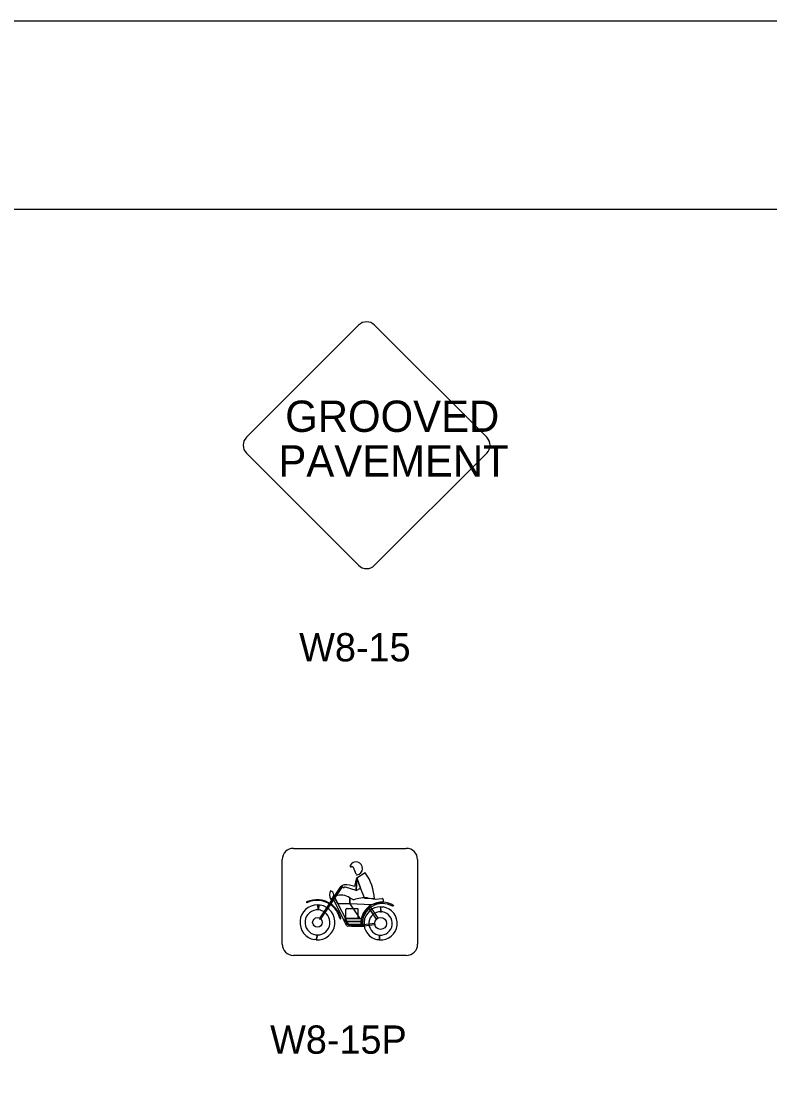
# Model space of a CAD drawing. Extents: x 42133 to 45533, y 41351 to 47951.
# Drawn here: x 44937.5 to 45136.1, y 47671.7 to 47951.4 of the extents above; entities that cross this region are included whole.
import ezdxf

# ---------------------------------------------------------------- set-up
doc = ezdxf.new("R2010")
doc.units = 0
for name, color, linetype in [('#plot_shape', 7, 'Continuous'), ('P_ODOT_PLAN_Border', 7, 'Continuous'), ('P_TRAF_SIGN_SignDetails', 7, 'Continuous')]:
    doc.layers.add(name, color=color, linetype=linetype)

msp = doc.modelspace()

# ---------------------------------------------------------------- linework, layer by layer
at = {"layer": '#plot_shape'}
msp.add_lwpolyline([(43833.34, 46851.35), (45533.34, 46851.35), (45533.34, 47951.35), (43833.34, 47951.35)], close=True, dxfattribs=at)
at = {"layer": 'P_ODOT_PLAN_Border'}
msp.add_lwpolyline([(43908.34, 46901.35), (45508.34, 46901.35), (45508.34, 47901.35), (43908.34, 47901.35)], close=True, dxfattribs=at)
at = {"layer": 'P_TRAF_SIGN_SignDetails'}
for p, q in [((45027.03, 47870.64), (44997.29, 47840.9)), ((45061.02, 47840.9), (45031.28, 47870.64)), ((44997.29, 47836.67), (45027.04, 47806.92)), ((45031.28, 47806.92), (45061.02, 47836.67)), ((45009.75, 47731.79), (45039.69, 47731.79)), ((45006.75, 47706.37), (45006.75, 47728.8)), ((45042.68, 47728.8), (45042.68, 47706.37)), ((45025.46, 47726.85), (45025.03, 47726.85)), ((45025.46, 47726.85), (45025.03, 47726.85)), ((45026.35, 47724.9), (45025.71, 47726.67)), ((45026.35, 47724.9), (45025.71, 47726.67)), ((45016.63, 47713.12), (45022.44, 47721.72)), ((45022.68, 47721.54), (45016.88, 47712.93)), ((45022.44, 47721.72), (45022.68, 47721.54)), ((45026.02, 47721.66), (45026.54, 47723.95)), ((45026.43, 47720.58), (45026.54, 47723.95)), ((45026.54, 47723.95), (45026.43, 47720.58)), ((45026.54, 47723.95), (45027.51, 47721.19)), ((45020.61, 47718.75), (45020.94, 47719.16)), ((45021.52, 47717.06), (45020.61, 47718.75)), ((45020.63, 47718.74), (45020.97, 47719.15)), ((45020.97, 47719.15), (45020.63, 47718.74)), ((45026.43, 47720.58), (45023.57, 47721.47)), ((45016.83, 47716.72), (45016.13, 47716.77)), ((45016.13, 47716.77), (45016.83, 47716.72)), ((45016.41, 47715.45), (45016.48, 47716.75)), ((45016.48, 47716.75), (45016.41, 47715.45)), ((45020.4, 47718.23), (45020.69, 47718.68)), ((45023.95, 47711.26), (45020.4, 47718.23)), ((45020.69, 47718.68), (45024.32, 47711.56)), ((45024.7, 47717.06), (45021.52, 47717.06)), ((45024.7, 47718.67), (45025.8, 47718.1)), ((45024.7, 47718.65), (45024.7, 47717.06)), ((45031.23, 47718.35), (45028.66, 47718.49)), ((45029.43, 47718.63), (45031.42, 47718.32)), ((45029.85, 47715.88), (45030.2, 47716.17)), ((45030.2, 47716.17), (45032.14, 47713.29)), ((45031.42, 47718.32), (45033.25, 47718.47)), ((45033.12, 47714.95), (45032.87, 47716.28)), ((45032.87, 47716.28), (45033.51, 47716.23)), ((45033.12, 47714.95), (45032.87, 47716.28)), ((45033.54, 47718.2), (45033.54, 47717.45)), ((45036.39, 47716.55), (45036.04, 47716.43)), ((45016.99, 47715.35), (45016.41, 47715.45)), ((45016.88, 47712.93), (45016.63, 47713.12)), ((45023.62, 47713.21), (45023.62, 47715.56)), ((45026.79, 47713.19), (45023.62, 47713.19)), ((45023.89, 47715.83), (45026.79, 47715.83)), ((45026.79, 47715.83), (45026.79, 47713.19)), ((45031.77, 47713.03), (45029.85, 47715.88)), ((45032.14, 47713.29), (45031.77, 47713.03)), ((45033.38, 47714.92), (45032.87, 47714.97)), ((45028.38, 47711.12), (45024.19, 47711.12)), ((45024.32, 47711.56), (45028.29, 47711.56)), ((45028.38, 47711.12), (45025.14, 47711.12)), ((45025.14, 47711.12), (45028.38, 47711.12)), ((45028.04, 47711.57), (45027.6, 47711.56)), ((45028.29, 47711.56), (45031.27, 47711.92)), ((45028.38, 47711.12), (45028.29, 47711.56)), ((45028.29, 47711.56), (45028.38, 47711.12)), ((45031.31, 47711.48), (45028.38, 47711.12)), ((45031.27, 47711.92), (45031.31, 47711.48)), ((45015.78, 47707.51), (45015.35, 47707.56)), ((45015.59, 47708.86), (45016.13, 47708.81)), ((45015.78, 47707.51), (45016.13, 47708.81)), ((45016.13, 47708.81), (45015.78, 47707.51)), ((45032.54, 47707.47), (45032.09, 47707.52)), ((45032.16, 47708.85), (45032.6, 47708.78)), ((45032.54, 47707.47), (45032.6, 47708.78)), ((45032.6, 47708.78), (45032.54, 47707.47)), ((45039.69, 47703.38), (45009.75, 47703.38))]:
    msp.add_line(p, q, dxfattribs=at)
for points in [[(45028.66, 47718.49), (45027.51, 47721.19), (45026.54, 47723.95), (45028.79, 47725.34)], [(45026.43, 47720.58), (45027.51, 47721.19), (45026.54, 47723.95)], [(45016.41, 47715.45), (45016.13, 47716.77), (45016.48, 47716.75)], [(45021.79, 47717.06), (45021.52, 47717.06), (45021.61, 47716.88)], [(45033.54, 47717.45), (45030.45, 47716.76), (45024.7, 47717.06), (45024.71, 47718.67)], [(45025.36, 47716.11), (45025.56, 47715.83), (45025.24, 47715.83)], [(45032.87, 47716.28), (45032.87, 47714.97), (45033.12, 47714.95)]]:
    msp.add_lwpolyline(points, dxfattribs=at)
for points in [[(45026.54, 47723.95), (45026.43, 47720.58), (45027.51, 47721.19)], [(45024.72, 47717.07), (45027.35, 47713.19), (45027.77, 47713.19), (45029.01, 47715.43), (45030.45, 47716.76)], [(45023.48, 47713.2), (45027.83, 47713.2), (45027.83, 47712.41), (45023.48, 47712.41)], [(45023.88, 47712.41), (45027.98, 47712.41), (45027.98, 47711.56), (45023.88, 47711.56)]]:
    msp.add_lwpolyline(points, close=True, dxfattribs=at)
for centre, radius in [((45016.13, 47712.13), 1.28), ((45032.87, 47711.87), 1.6)]:
    msp.add_circle(centre, radius, dxfattribs=at)
for centre, radius, start, end in [((45029.15, 47868.53), 3, 45, 135), ((44999.41, 47838.78), 3, 135, 225), ((45058.9, 47838.78), 3, 315, 45), ((45029.15, 47809.04), 3, 225, 315), ((45009.75, 47728.8), 2.99, 90, 180), ((45039.68, 47728.8), 2.99, 360, 90), ((45025.03, 47727.12), 0.27, 153.1842, 270), ((45025.03, 47727.12), 0.27, 153.1842, 270), ((45026.35, 47726.45), 1.75, 279.9095, 153.1842), ((45026.35, 47726.45), 1.75, 279.9095, 153.1842), ((45025.46, 47726.58), 0.27, 20, 90), ((45026.61, 47725), 0.27, 200, 279.9095), ((45026.61, 47725), 0.27, 200, 279.9095), ((45018.71, 47717.85), 12.53, 2.1257, 36.3739), ((45023.42, 47720.67), 1.44, 99.6583, 132.9805), ((45022.78, 47721.38), 0.188, 46.8617, 122.8102), ((45023.12, 47721.55), 0.212, 188.1341, 341.5566), ((45023.42, 47714.03), 8.06, 71.1813, 91.7386), ((45023.44, 47721.32), 0.191, 48.9488, 128.037), ((45022.36, 47719.4), 3.02, 158.481, 200.801), ((45019.34, 47719.42), 1.11, 280.221, 79.061), ((45022.3, 47714.91), 4.45, 57.5072, 107.4391), ((45016.13, 47712.13), 4.64, 90, 260.2571), ((45013.3, 47717.47), 0.12, 114.8077, 260.8072), ((45015.98, 47711.66), 6.51, 54.7755, 114.778), ((45015.98, 47711.66), 6.3, 55.8164, 115.3015), ((45016.13, 47712.13), 4.64, 265.6936, 81.3872), ((45015.98, 47711.66), 6.3, 14.4017, 55.8164), ((45015.98, 47711.66), 6.51, 13.8277, 54.7755), ((45021.79, 47716.88), 0.18, 90, 180), ((45025.22, 47716.01), 0.18, 273.0113, 36.4444), ((45028.7, 47710.67), 8, 84.7402, 111.3141), ((45033.25, 47711.84), 5.66, 56.323, 183.005), ((45033.36, 47711.82), 5.33, 59.7827, 182.6294), ((45032.87, 47711.87), 4.41, 90, 259.8636), ((45032.87, 47711.87), 4.41, 265.8146, 81.6292), ((45033.27, 47718.2), 0.27, 360, 94.5392), ((45016.13, 47712.13), 3.32, 85.3033, 260.6065), ((45016.13, 47712.13), 3.32, 270, 75.0279), ((45022.19, 47713.22), 0.109, 172.4604, 358.5245), ((45023.89, 47715.56), 0.27, 90, 179.9596), ((45032.87, 47711.87), 3.1, 90, 256.7853), ((45032.87, 47711.87), 3.1, 265.1774, 80.3548), ((45024.19, 47711.39), 0.27, 207, 270), ((45009.75, 47706.37), 2.99, 180, 270), ((45039.69, 47706.37), 2.99, 270, 360)]:
    msp.add_arc(centre, radius, start, end, dxfattribs=at)

# ---------------------------------------------------------------- texts
for s, height, p in [('GROOVED', 8.305, (45007.57, 47842.32)), ('PAVEMENT', 8.305, (45005.77, 47830.46)), ('W8-15', 7.5, (45011.28, 47781.41)), ('W8-15P', 7.5, (45003.57, 47677.28))]:
    msp.add_text(s, height=height, dxfattribs=at).set_placement(p)

doc.saveas('drawing.dxf')
